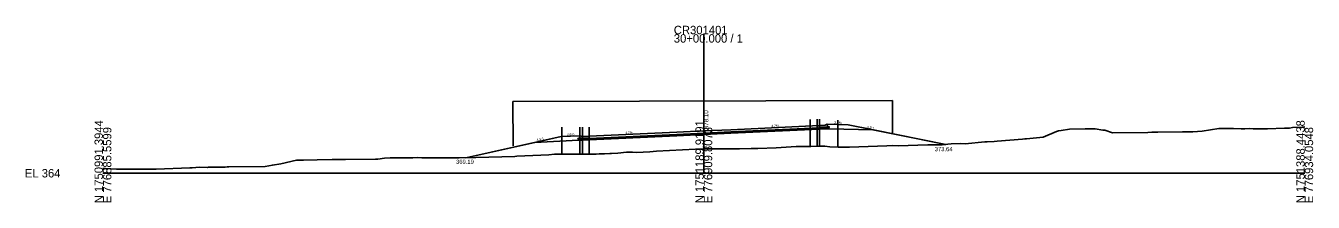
# Model space of a CAD drawing. Extents: x 765710 to 788731, y 1743078 to 1754528.
# Drawn here: x 787302.9 to 787731.5, y 1745452.4 to 1745511.3 of the extents above; entities that cross this region are included whole.
import ezdxf

# ---------------------------------------------------------------- set-up
doc = ezdxf.new("R2010")
doc.units = 0
for name, color, linetype in [('ALI_DESIGN_ML', 7, 'Continuous'), ('ControlPoints', 7, 'Continuous'), ('Observations', 7, 'Continuous'), ('Setups', 7, 'Continuous'), ('SHEET_BORDER', 7, 'Continuous'), ('SHEET_DATE_DGN_TX', 7, 'Continuous'), ('SHEET_PLOTTING_SHAPE', 7, 'Continuous'), ('SHEET_PROJ_NUMBER', 7, 'Continuous'), ('SHEET_TITLE_BLOCK_TX', 7, 'Continuous'), ('SHEET_WORK_NUMBER', 7, 'Continuous'), ('TS_ANGLE_REPOSE', 7, 'Continuous'), ('TS_BACKBONE', 7, 'Continuous'), ('TS_SIDE_SLOPE_LT', 7, 'Continuous'), ('TS_SUBGRADE', 7, 'Continuous'), ('TS_TITLE_BLOCK_TX', 7, 'Continuous')]:
    doc.layers.add(name, color=color, linetype=linetype)

msp = doc.modelspace()

# ---------------------------------------------------------------- linework, layer by layer
at = {"layer": 'ALI_DESIGN_ML'}
for p, q in [((787564.03, 1745480.03), (787564.03, 1745471.03)), ((787490.48, 1745477.42), (787490.48, 1745468.42))]:
    msp.add_line(p, q, dxfattribs=at)
at = {"layer": 'ControlPoints'}
msp.add_lwpolyline([(787328.64, 1745463.7), (787329.48, 1745463.69), (787333.12, 1745463.46), (787340.26, 1745463.48), (787343.37, 1745463.46), (787344.62, 1745463.5), (787346.31, 1745463.46), (787357.56, 1745463.86), (787358.36, 1745463.94), (787360.73, 1745464.12), (787363.39, 1745464.06), (787363.73, 1745464.09), (787366.96, 1745464.11), (787369.29, 1745464.16), (787369.96, 1745464.25), (787370.59, 1745464.26), (787382.6, 1745464.36), (787385.05, 1745464.83), (787387.82, 1745465.24), (787393.08, 1745466.48), (787394.18, 1745466.48), (787395.43, 1745466.51), (787399.91, 1745466.57), (787404.9, 1745466.65), (787407.2, 1745466.63), (787408.3, 1745466.65), (787409.37, 1745466.66), (787419.3, 1745466.83), (787420.17, 1745466.84), (787422.38, 1745467.15), (787424.27, 1745467.18), (787425.64, 1745467.19), (787431.78, 1745467.27), (787433.24, 1745467.34), (787434.83, 1745467.28), (787444.41, 1745467.26), (787447.15, 1745467.26), (787452.71, 1745467.32), (787465.72, 1745467.72), (787466.45, 1745467.77), (787474.41, 1745468.13), (787477.05, 1745468.27), (787478.89, 1745468.42), (787480.62, 1745468.46), (787492.35, 1745468.41), (787492.82, 1745468.48), (787493.77, 1745468.56), (787495.53, 1745468.6), (787497.34, 1745468.67), (787497.95, 1745468.68), (787500.04, 1745468.79), (787502.92, 1745469.14), (787504.85, 1745469.18), (787506.24, 1745469.06), (787510.62, 1745469.29), (787512.89, 1745469.45), (787525.89, 1745470.15), (787528.64, 1745470.23), (787530.31, 1745470.28), (787531.81, 1745470.28), (787535.07, 1745470.2), (787537.43, 1745470.22), (787539.08, 1745470.23), (787540.51, 1745470.2), (787544.34, 1745470.36), (787546.6, 1745470.34), (787552.76, 1745470.54), (787559.34, 1745470.97), (787564.26, 1745471.03), (787566.83, 1745471.15), (787568.95, 1745471.08), (787570.57, 1745470.95), (787573.37, 1745470.84), (787577.07, 1745470.81), (787589.6, 1745471.27), (787591.59, 1745471.32), (787593.35, 1745471.25), (787603.22, 1745471.56), (787604.46, 1745471.58), (787607.92, 1745471.61), (787609.9, 1745471.75), (787611.01, 1745471.85), (787614.14, 1745472.03), (787615.57, 1745471.95), (787622.18, 1745472.53), (787622.95, 1745472.6), (787625.32, 1745472.66), (787626.25, 1745472.74), (787634.75, 1745473.45), (787635.43, 1745473.52), (787636.01, 1745473.54), (787641.58, 1745474.13), (787646.01, 1745475.99), (787646.66, 1745476.27), (787647.55, 1745476.38), (787650.37, 1745476.78), (787655.58, 1745476.85), (787658.9, 1745476.87), (787661.43, 1745476.47), (787662.08, 1745476.44), (787664.67, 1745475.57), (787676.47, 1745475.72), (787677.79, 1745475.75), (787679.71, 1745475.78), (787687.92, 1745475.87), (787691.41, 1745475.89), (787694.54, 1745476.12), (787700.08, 1745476.97), (787704.89, 1745476.97), (787707.51, 1745476.96), (787708.65, 1745476.9), (787710.33, 1745476.98), (787711.48, 1745476.9), (787712.18, 1745476.88), (787713.01, 1745476.9), (787714.47, 1745476.93), (787716.22, 1745476.94), (787721.94, 1745477.1), (787723.57, 1745477.16), (787724.52, 1745477.34), (787727.82, 1745477.51), (787728.64, 1745477.55)], dxfattribs=at)
at = {"layer": 'Setups'}
for p, q in [((787528.64, 1745462.1), (787528.64, 1745508.45)), ((787328.64, 1745462.1), (787528.64, 1745462.1)), ((787528.64, 1745462.1), (787728.64, 1745462.1))]:
    msp.add_line(p, q, dxfattribs=at)
at = {"layer": 'SHEET_DATE_DGN_TX'}
for p, q in [((787566.99, 1745478), (787567, 1745477.5)), ((787567, 1745477.5), (787569.75, 1745477.62)), ((787569.75, 1745477.62), (787569.74, 1745478.46)), ((787487.37, 1745473.77), (787487.37, 1745474.6)), ((787490.48, 1745473.91), (787487.37, 1745473.77)), ((787490.48, 1745474.41), (787490.48, 1745473.91))]:
    msp.add_line(p, q, dxfattribs=at)
at = {"layer": 'SHEET_PLOTTING_SHAPE'}
for p, q in [((787569.75, 1745477.62), (787569.74, 1745478.46)), ((787570.25, 1745477.65), (787569.75, 1745477.62)), ((787570.39, 1745477.4), (787570.25, 1745477.65)), ((787486.73, 1745473.49), (787486.87, 1745473.75)), ((787486.87, 1745473.5), (787486.73, 1745473.49)), ((787486.87, 1745473.75), (787487.37, 1745473.77)), ((787490.48, 1745473.66), (787486.87, 1745473.5)), ((787487.37, 1745473.77), (787487.37, 1745474.6)), ((787519.64, 1745475.03), (787490.48, 1745473.66)), ((787519.64, 1745475.03), (787528.64, 1745475.45)), ((787528.64, 1745475.45), (787537.64, 1745475.87)), ((787537.64, 1745475.87), (787567, 1745477.25)), ((787567, 1745477.25), (787570.25, 1745477.4)), ((787570.25, 1745477.4), (787570.39, 1745477.4))]:
    msp.add_line(p, q, dxfattribs=at)
at = {"layer": 'SHEET_PROJ_NUMBER'}
for p, q in [((787465.11, 1745486.04), (787591.38, 1745486.35)), ((787591.38, 1745486.35), (787591.41, 1745475.28)), ((787465.15, 1745471.22), (787465.11, 1745486.04))]:
    msp.add_line(p, q, dxfattribs=at)
at = {"layer": 'SHEET_TITLE_BLOCK_TX'}
for p, q in [((787519.64, 1745474.61), (787490.49, 1745473.25)), ((787519.64, 1745474.61), (787528.64, 1745475.03)), ((787528.64, 1745475.03), (787537.64, 1745475.45)), ((787537.64, 1745475.45), (787567, 1745476.83)), ((787567, 1745476.83), (787569, 1745476.92)), ((787569, 1745476.92), (787570.25, 1745476.89)), ((787488.12, 1745473.14), (787486.87, 1745473.08)), ((787490.49, 1745473.25), (787488.12, 1745473.14))]:
    msp.add_line(p, q, dxfattribs=at)
at = {"layer": 'SHEET_WORK_NUMBER'}
for p, q in [((787537.64, 1745476.62), (787566.99, 1745478)), ((787566.99, 1745478), (787568.99, 1745478.09)), ((787568.99, 1745478.17), (787569.74, 1745478.46)), ((787568.99, 1745478.09), (787568.99, 1745478.17)), ((787569.74, 1745478.46), (787576.67, 1745478.24)), ((787576.67, 1745478.24), (787609.19, 1745471.7)), ((787481.15, 1745474.36), (787449.43, 1745467.29)), ((787487.37, 1745474.6), (787481.15, 1745474.36)), ((787488.22, 1745474.39), (787487.37, 1745474.6)), ((787490.48, 1745474.41), (787488.22, 1745474.31)), ((787488.22, 1745474.31), (787488.22, 1745474.39)), ((787519.64, 1745475.78), (787490.48, 1745474.41)), ((787519.64, 1745475.78), (787528.64, 1745476.2)), ((787528.64, 1745476.2), (787537.64, 1745476.62))]:
    msp.add_line(p, q, dxfattribs=at)
at = {"layer": 'TS_ANGLE_REPOSE'}
for p, q in [((787566.32, 1745480.12), (787566.32, 1745471.12)), ((787567.18, 1745480.14), (787567.18, 1745471.14)), ((787487.37, 1745477.43), (787487.37, 1745468.43)), ((787488.22, 1745477.43), (787488.22, 1745468.43))]:
    msp.add_line(p, q, dxfattribs=at)
at = {"layer": 'TS_SIDE_SLOPE_LT'}
for p, q in [((787486.87, 1745473.5), (787486.87, 1745473.08)), ((787570.25, 1745476.89), (787585.09, 1745476.55)), ((787486.87, 1745473.08), (787472.35, 1745472.4))]:
    msp.add_line(p, q, dxfattribs=at)
msp.add_lwpolyline([(787570.25, 1745477.4), (787570.25, 1745476.89)], dxfattribs=at)
at = {"layer": 'TS_SUBGRADE'}
for points in [[(787519.64, 1745475.78), (787490.48, 1745474.41), (787488.22, 1745474.31), (787488.22, 1745474.39), (787487.37, 1745474.6), (787487.37, 1745473.77), (787486.87, 1745473.75), (787486.73, 1745473.49), (787486.87, 1745473.5), (787490.48, 1745473.66), (787519.64, 1745475.03), (787528.64, 1745475.45), (787537.64, 1745475.87), (787567, 1745477.25), (787570.25, 1745477.4), (787570.39, 1745477.4), (787570.25, 1745477.65), (787569.75, 1745477.62), (787569.74, 1745478.46), (787568.99, 1745478.17), (787568.99, 1745478.09), (787566.99, 1745478), (787537.64, 1745476.62), (787528.64, 1745476.2)], [(787569.74, 1745478.46), (787576.67, 1745478.24), (787585.09, 1745476.55), (787570.25, 1745476.89), (787570.25, 1745477.4), (787570.39, 1745477.4), (787570.25, 1745477.65), (787569.75, 1745477.62)], [(787567, 1745476.83), (787569, 1745476.92), (787570.25, 1745476.89), (787585.09, 1745476.55), (787609.19, 1745471.7), (787607.92, 1745471.61), (787604.46, 1745471.58), (787603.22, 1745471.56), (787593.35, 1745471.25), (787591.59, 1745471.32), (787589.6, 1745471.27), (787577.07, 1745470.81), (787573.37, 1745470.84), (787570.57, 1745470.95), (787568.95, 1745471.08), (787566.83, 1745471.15), (787564.26, 1745471.03), (787559.34, 1745470.97), (787552.76, 1745470.54), (787546.6, 1745470.34), (787544.34, 1745470.36), (787540.51, 1745470.2), (787539.08, 1745470.23), (787537.43, 1745470.22), (787535.07, 1745470.2), (787531.81, 1745470.28), (787530.31, 1745470.28), (787528.64, 1745470.23), (787525.89, 1745470.15), (787512.89, 1745469.45), (787510.62, 1745469.29), (787506.24, 1745469.06), (787504.85, 1745469.18), (787502.92, 1745469.14), (787500.04, 1745468.79), (787497.95, 1745468.68), (787497.34, 1745468.67), (787495.53, 1745468.6), (787493.77, 1745468.56), (787492.82, 1745468.48), (787492.35, 1745468.41), (787480.62, 1745468.46), (787478.89, 1745468.42), (787477.05, 1745468.27), (787474.41, 1745468.13), (787466.45, 1745467.77), (787465.72, 1745467.72), (787452.71, 1745467.32), (787449.43, 1745467.29), (787472.35, 1745472.4), (787486.87, 1745473.08), (787488.12, 1745473.14), (787490.49, 1745473.25), (787519.64, 1745474.61), (787528.64, 1745475.03), (787537.64, 1745475.45)], [(787481.15, 1745474.36), (787472.35, 1745472.4), (787486.87, 1745473.08), (787486.87, 1745473.5), (787486.73, 1745473.49), (787486.87, 1745473.75), (787487.37, 1745473.77), (787487.37, 1745474.6)], [(787567, 1745476.83), (787569, 1745476.92), (787570.25, 1745476.89), (787570.25, 1745477.4), (787567, 1745477.25), (787537.64, 1745475.87), (787528.64, 1745475.45), (787519.64, 1745475.03), (787490.48, 1745473.66), (787486.87, 1745473.5), (787486.87, 1745473.08), (787488.12, 1745473.14), (787490.49, 1745473.25), (787519.64, 1745474.61), (787528.64, 1745475.03), (787537.64, 1745475.45)]]:
    msp.add_lwpolyline(points, close=True, dxfattribs=at)
at = {"layer": 'TS_TITLE_BLOCK_TX'}
for p, q in [((787573.25, 1745479.84), (787573.25, 1745470.84)), ((787481.38, 1745477.45), (787481.38, 1745468.45))]:
    msp.add_line(p, q, dxfattribs=at)

# ---------------------------------------------------------------- texts
at = {"layer": 'Observations'}
for s, p in [('373.64', (787605.5, 1745469.44)), ('369.19', (787446.17, 1745465.22))]:
    msp.add_text(s, height=1.4, rotation=0.1402, dxfattribs=at).set_placement(p)
at = {"layer": 'Setups'}
for s, p in [('30+00.000 / 1', (787518.64, 1745505.65)), ('CR301401', (787518.64, 1745508.45)), ('EL 364', (787302.64, 1745460.7))]:
    msp.add_text(s, height=2.8, dxfattribs=at).set_placement(p)
for s, p in [('N 1750991.3944', (787328.64, 1745452.1)), ('N 1751189.9191', (787528.64, 1745452.1)), ('N 1751388.4438', (787728.64, 1745452.1)), ('E 776885.5599', (787331.44, 1745452.1)), ('E 776909.8073', (787531.44, 1745452.1)), ('E 776934.0548', (787731.44, 1745452.1))]:
    msp.add_text(s, height=2.8, rotation=90, dxfattribs=at).set_placement(p)
at = {"layer": 'SHEET_BORDER'}
for s, rotation, p in [('4.7%', 2.6795, (787551.11, 1745477.45)), ('3.4%', 358.2186, (787572.02, 1745478.59)), ('4.9:1', 348.6304, (787582.85, 1745477.2)), ('4.5:1', 12.5772, (787473.08, 1745472.77)), ('3.6%', 2.2029, (787483.04, 1745474.64)), ('4.7%', 2.6795, (787502.48, 1745475.18))]:
    msp.add_text(s, height=0.8, rotation=rotation, dxfattribs=at).set_placement(p)
at = {"layer": 'TS_BACKBONE'}
msp.add_text(' 378.10', height=1.5, rotation=90.1402, dxfattribs=at).set_placement((787530.14, 1745476.2))

doc.saveas('drawing.dxf')
